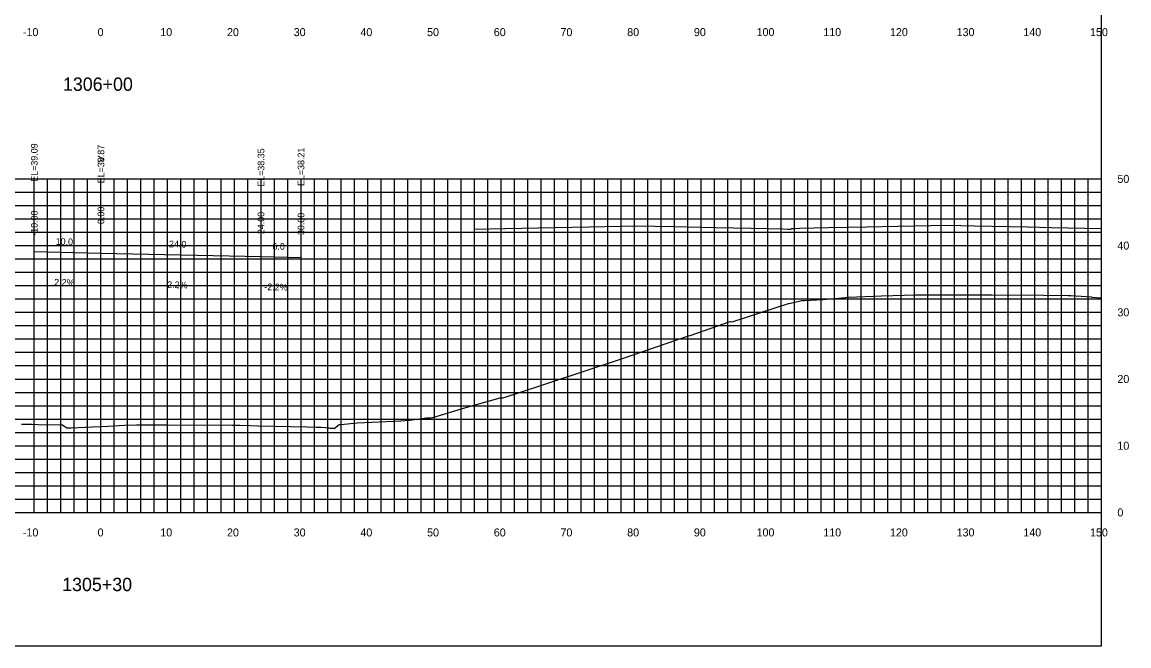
# Model space of a CAD drawing. Extents: x 1797714 to 1804825, y 249015 to 250269.
# Drawn here: x 1804292.3 to 1804458.3, y 249628.2 to 249721.7 of the extents above; entities that cross this region are included whole.
import ezdxf

# ---------------------------------------------------------------- set-up
doc = ezdxf.new("R2010")
doc.units = 0
for name, color, linetype in [('1', 7, 'Continuous'), ('10', 7, 'Continuous'), ('3', 7, 'Continuous'), ('31', 7, 'Continuous'), ('4', 7, 'Continuous'), ('60', 7, 'Continuous'), ('CL-CNST', 7, 'Continuous'), ('Level 62', 7, 'Continuous'), ('M-ROADS', 7, 'Continuous'), ('WEARING', 7, 'Continuous')]:
    doc.layers.add(name, color=color, linetype=linetype)

msp = doc.modelspace()

# ---------------------------------------------------------------- linework, layer by layer
for p, q in [((1804294.16, 249687.26), (1804294.16, 249689.26)), ((1804304.16, 249687.04), (1804304.16, 249689.04)), ((1804328.16, 249686.51), (1804328.16, 249688.51)), ((1804334.16, 249686.38), (1804334.16, 249688.38))]:
    msp.add_line(p, q)
msp.add_lwpolyline([(1804154.16, 249628.17), (1804454.16, 249628.17), (1804454.16, 249818.17), (1804154.16, 249818.17)], close=True)
at = {"layer": '60'}
for p, q in [((1804454.16, 249648.17), (1804454.16, 249698.17)), ((1804454.22, 249698.17), (1804454.16, 249698.17)), ((1804454.22, 249688.17), (1804454.16, 249688.17)), ((1804454.22, 249678.17), (1804454.16, 249678.17)), ((1804454.22, 249668.17), (1804454.16, 249668.17)), ((1804454.22, 249658.17), (1804454.16, 249658.17)), ((1804154.16, 249648.17), (1804454.16, 249648.17)), ((1804294.16, 249648.11), (1804294.16, 249648.17)), ((1804304.16, 249648.11), (1804304.16, 249648.17)), ((1804314.16, 249648.11), (1804314.16, 249648.17)), ((1804324.16, 249648.11), (1804324.16, 249648.17)), ((1804334.16, 249648.11), (1804334.16, 249648.17)), ((1804344.16, 249648.11), (1804344.16, 249648.17)), ((1804354.16, 249648.11), (1804354.16, 249648.17)), ((1804364.16, 249648.11), (1804364.16, 249648.17)), ((1804374.16, 249648.11), (1804374.16, 249648.17)), ((1804384.16, 249648.11), (1804384.16, 249648.17)), ((1804394.16, 249648.11), (1804394.16, 249648.17)), ((1804404.16, 249648.11), (1804404.16, 249648.17)), ((1804414.16, 249648.11), (1804414.16, 249648.17)), ((1804424.16, 249648.11), (1804424.16, 249648.17)), ((1804434.16, 249648.11), (1804434.16, 249648.17)), ((1804444.16, 249648.11), (1804444.16, 249648.17)), ((1804454.16, 249648.11), (1804454.16, 249648.17)), ((1804454.22, 249648.17), (1804454.16, 249648.17))]:
    msp.add_line(p, q, dxfattribs=at)
at = {"layer": 'CL-CNST'}
for points in [[(1804360.18, 249690.63), (1804364.73, 249690.73), (1804372.24, 249690.89), (1804377.4, 249691), (1804384.31, 249691.15), (1804390.08, 249691.02), (1804396.37, 249690.88), (1804401.64, 249690.77), (1804406.42, 249690.66), (1804407.1, 249690.64), (1804407.67, 249690.63)], [(1804294.16, 249687.26), (1804304.16, 249687.04), (1804328.16, 249686.51), (1804334.16, 249686.38)]]:
    msp.add_lwpolyline(points, dxfattribs=at)
at = {"layer": 'Level 62'}
for p, q in [((1804154.16, 249698.17), (1804454.16, 249698.17)), ((1804294.16, 249648.17), (1804294.16, 249698.17)), ((1804296.16, 249648.17), (1804296.16, 249698.17)), ((1804298.16, 249648.17), (1804298.16, 249698.17)), ((1804300.16, 249648.17), (1804300.16, 249698.17)), ((1804302.16, 249648.17), (1804302.16, 249698.17)), ((1804304.16, 249648.17), (1804304.16, 249698.17)), ((1804306.16, 249648.17), (1804306.16, 249698.17)), ((1804308.16, 249648.17), (1804308.16, 249698.17)), ((1804310.16, 249648.17), (1804310.16, 249698.17)), ((1804312.16, 249648.17), (1804312.16, 249698.17)), ((1804314.16, 249648.17), (1804314.16, 249698.17)), ((1804316.16, 249648.17), (1804316.16, 249698.17)), ((1804318.16, 249648.17), (1804318.16, 249698.17)), ((1804320.16, 249648.17), (1804320.16, 249698.17)), ((1804322.16, 249648.17), (1804322.16, 249698.17)), ((1804324.16, 249648.17), (1804324.16, 249698.17)), ((1804326.16, 249648.17), (1804326.16, 249698.17)), ((1804328.16, 249648.17), (1804328.16, 249698.17)), ((1804330.16, 249648.17), (1804330.16, 249698.17)), ((1804332.16, 249648.17), (1804332.16, 249698.17)), ((1804334.16, 249648.17), (1804334.16, 249698.17)), ((1804336.16, 249648.17), (1804336.16, 249698.17)), ((1804338.16, 249648.17), (1804338.16, 249698.17)), ((1804340.16, 249648.17), (1804340.16, 249698.17)), ((1804342.16, 249648.17), (1804342.16, 249698.17)), ((1804344.16, 249648.17), (1804344.16, 249698.17)), ((1804346.16, 249648.17), (1804346.16, 249698.17)), ((1804348.16, 249648.17), (1804348.16, 249698.17)), ((1804350.16, 249648.17), (1804350.16, 249698.17)), ((1804352.16, 249648.17), (1804352.16, 249698.17)), ((1804354.16, 249648.17), (1804354.16, 249698.17)), ((1804356.16, 249648.17), (1804356.16, 249698.17)), ((1804358.16, 249648.17), (1804358.16, 249698.17)), ((1804360.16, 249648.17), (1804360.16, 249698.17)), ((1804362.16, 249648.17), (1804362.16, 249698.17)), ((1804364.16, 249648.17), (1804364.16, 249698.17)), ((1804366.16, 249648.17), (1804366.16, 249698.17)), ((1804368.16, 249648.17), (1804368.16, 249698.17)), ((1804370.16, 249648.17), (1804370.16, 249698.17)), ((1804372.16, 249648.17), (1804372.16, 249698.17)), ((1804374.16, 249648.17), (1804374.16, 249698.17)), ((1804376.16, 249648.17), (1804376.16, 249698.17)), ((1804378.16, 249648.17), (1804378.16, 249698.17)), ((1804380.16, 249648.17), (1804380.16, 249698.17)), ((1804382.16, 249648.17), (1804382.16, 249698.17)), ((1804384.16, 249648.17), (1804384.16, 249698.17)), ((1804386.16, 249648.17), (1804386.16, 249698.17)), ((1804388.16, 249648.17), (1804388.16, 249698.17)), ((1804390.16, 249648.17), (1804390.16, 249698.17)), ((1804392.16, 249648.17), (1804392.16, 249698.17)), ((1804394.16, 249648.17), (1804394.16, 249698.17)), ((1804396.16, 249648.17), (1804396.16, 249698.17)), ((1804398.16, 249648.17), (1804398.16, 249698.17)), ((1804400.16, 249648.17), (1804400.16, 249698.17)), ((1804402.16, 249648.17), (1804402.16, 249698.17)), ((1804404.16, 249648.17), (1804404.16, 249698.17)), ((1804406.16, 249648.17), (1804406.16, 249698.17)), ((1804408.16, 249648.17), (1804408.16, 249698.17)), ((1804410.16, 249648.17), (1804410.16, 249698.17)), ((1804412.16, 249648.17), (1804412.16, 249698.17)), ((1804414.16, 249648.17), (1804414.16, 249698.17)), ((1804416.16, 249648.17), (1804416.16, 249698.17)), ((1804418.16, 249648.17), (1804418.16, 249698.17)), ((1804420.16, 249648.17), (1804420.16, 249698.17)), ((1804422.16, 249648.17), (1804422.16, 249698.17)), ((1804424.16, 249648.17), (1804424.16, 249698.17)), ((1804426.16, 249648.17), (1804426.16, 249698.17)), ((1804428.16, 249648.17), (1804428.16, 249698.17)), ((1804430.16, 249648.17), (1804430.16, 249698.17)), ((1804432.16, 249648.17), (1804432.16, 249698.17)), ((1804434.16, 249648.17), (1804434.16, 249698.17)), ((1804436.16, 249648.17), (1804436.16, 249698.17)), ((1804438.16, 249648.17), (1804438.16, 249698.17)), ((1804440.16, 249648.17), (1804440.16, 249698.17)), ((1804442.16, 249648.17), (1804442.16, 249698.17)), ((1804444.16, 249648.17), (1804444.16, 249698.17)), ((1804446.16, 249648.17), (1804446.16, 249698.17)), ((1804448.16, 249648.17), (1804448.16, 249698.17)), ((1804450.16, 249648.17), (1804450.16, 249698.17)), ((1804452.16, 249648.17), (1804452.16, 249698.17)), ((1804454.16, 249648.17), (1804454.16, 249698.17)), ((1804154.16, 249696.17), (1804454.16, 249696.17)), ((1804154.16, 249694.17), (1804454.16, 249694.17)), ((1804154.16, 249692.17), (1804454.16, 249692.17)), ((1804154.16, 249690.17), (1804454.16, 249690.17)), ((1804154.16, 249688.17), (1804454.16, 249688.17)), ((1804154.16, 249686.17), (1804454.16, 249686.17)), ((1804154.16, 249684.17), (1804454.16, 249684.17)), ((1804154.16, 249682.17), (1804454.16, 249682.17)), ((1804154.16, 249680.17), (1804454.16, 249680.17)), ((1804154.16, 249678.17), (1804454.16, 249678.17)), ((1804154.16, 249676.17), (1804454.16, 249676.17)), ((1804154.16, 249674.17), (1804454.16, 249674.17)), ((1804154.16, 249672.17), (1804454.16, 249672.17)), ((1804154.16, 249670.17), (1804454.16, 249670.17)), ((1804154.16, 249668.17), (1804454.16, 249668.17)), ((1804154.16, 249666.17), (1804454.16, 249666.17)), ((1804154.16, 249664.17), (1804454.16, 249664.17)), ((1804154.16, 249662.17), (1804454.16, 249662.17)), ((1804154.16, 249660.17), (1804454.16, 249660.17)), ((1804154.16, 249658.17), (1804454.16, 249658.17)), ((1804154.16, 249656.17), (1804454.16, 249656.17)), ((1804154.16, 249654.17), (1804454.16, 249654.17)), ((1804154.16, 249652.17), (1804454.16, 249652.17)), ((1804154.16, 249650.17), (1804454.16, 249650.17)), ((1804154.16, 249648.17), (1804454.16, 249648.17))]:
    msp.add_line(p, q, dxfattribs=at)
at = {"layer": 'M-ROADS'}
msp.add_lwpolyline([(1804292.26, 249661.4), (1804292.67, 249661.4), (1804293.75, 249661.38), (1804293.8, 249661.38), (1804294.77, 249661.34), (1804298.37, 249661.3), (1804298.61, 249661.13), (1804299.04, 249660.86), (1804299.43, 249660.85), (1804299.46, 249660.85), (1804299.49, 249660.85), (1804299.53, 249660.84), (1804299.57, 249660.84), (1804299.62, 249660.84), (1804299.67, 249660.83), (1804299.7, 249660.83), (1804302.89, 249660.99), (1804305.25, 249661.11), (1804307.72, 249661.25), (1804309.5, 249661.28), (1804309.99, 249661.29), (1804310.24, 249661.29), (1804310.28, 249661.29), (1804311.37, 249661.29), (1804312.73, 249661.31), (1804314.01, 249661.3), (1804323.82, 249661.24), (1804324.98, 249661.24), (1804326.56, 249661.2), (1804327.75, 249661.17), (1804335.01, 249660.99), (1804336.45, 249660.95), (1804337.1, 249660.93), (1804337.16, 249660.93), (1804337.81, 249660.88), (1804338.14, 249660.85), (1804338.34, 249660.84), (1804338.47, 249660.82), (1804338.56, 249660.82), (1804338.64, 249660.81), (1804338.69, 249660.81), (1804338.73, 249660.8), (1804338.74, 249660.8), (1804338.77, 249660.8), (1804338.8, 249660.8), (1804338.83, 249660.79), (1804338.85, 249660.79), (1804338.87, 249660.79), (1804338.89, 249660.79), (1804338.9, 249660.79), (1804338.92, 249660.79), (1804338.93, 249660.78), (1804338.94, 249660.78), (1804338.95, 249660.78), (1804338.96, 249660.78), (1804338.97, 249660.78), (1804339.11, 249660.76), (1804339.7, 249661.21), (1804339.73, 249661.23), (1804339.76, 249661.26), (1804339.87, 249661.35), (1804339.9, 249661.36), (1804340.11, 249661.36), (1804342.57, 249661.61), (1804349.1, 249661.88), (1804349.17, 249661.88), (1804350.34, 249662), (1804350.46, 249662.02), (1804352.99, 249662.36), (1804353.36, 249662.35), (1804353.53, 249662.37), (1804353.6, 249662.36), (1804353.91, 249662.42), (1804358.85, 249663.88), (1804364, 249665.34), (1804364.05, 249665.34), (1804364.49, 249665.33), (1804365.81, 249665.78), (1804365.87, 249665.78), (1804382.19, 249671.19), (1804392.25, 249674.66), (1804392.49, 249674.67), (1804398.49, 249676.77), (1804398.79, 249676.75), (1804407.24, 249679.47), (1804407.37, 249679.47), (1804409.25, 249679.95), (1804409.6, 249679.94), (1804412.38, 249680.07), (1804414.24, 249680.24), (1804416.25, 249680.43), (1804421.19, 249680.62), (1804426.31, 249680.81), (1804428.74, 249680.8), (1804431.99, 249680.79), (1804437.71, 249680.78), (1804445.46, 249680.73), (1804449.16, 249680.71), (1804449.59, 249680.68), (1804452.68, 249680.47), (1804452.74, 249680.46), (1804454.16, 249680.35)], dxfattribs=at)
at = {"layer": 'WEARING'}
msp.add_lwpolyline([(1804407.67, 249690.74), (1804408.24, 249690.75), (1804408.93, 249690.77), (1804413.24, 249690.86), (1804418.98, 249690.98), (1804423.65, 249691.08), (1804431.04, 249691.24), (1804435.15, 249691.14), (1804443.1, 249690.97), (1804446.65, 249690.89), (1804454.16, 249690.72)], dxfattribs=at)

# ---------------------------------------------------------------- texts
at = {"layer": '1'}
for s, p in [('1306+00', (1804298.46, 249711.37)), ('1305+30', (1804298.34, 249636.37))]:
    msp.add_text(s, height=2, dxfattribs=at).set_placement(p)
at = {"layer": '10'}
for s, p in [('-10', (1804292.46, 249719.57)), ('0', (1804303.66, 249719.57)), ('10', (1804313.06, 249719.57)), ('20', (1804323.06, 249719.57)), ('30', (1804333.06, 249719.57)), ('40', (1804343.06, 249719.57)), ('50', (1804353.06, 249719.57)), ('60', (1804363.06, 249719.57)), ('70', (1804373.06, 249719.57)), ('80', (1804383.06, 249719.57)), ('90', (1804393.06, 249719.57)), ('100', (1804402.46, 249719.57)), ('110', (1804412.46, 249719.57)), ('120', (1804422.46, 249719.57)), ('130', (1804432.46, 249719.57)), ('140', (1804442.46, 249719.57)), ('150', (1804452.46, 249719.57)), ('-10', (1804292.46, 249644.57)), ('0', (1804303.66, 249644.57)), ('10', (1804313.06, 249644.57)), ('20', (1804323.06, 249644.57)), ('30', (1804333.06, 249644.57)), ('40', (1804343.06, 249644.57)), ('50', (1804353.06, 249644.57)), ('60', (1804363.06, 249644.57)), ('70', (1804373.06, 249644.57)), ('80', (1804383.06, 249644.57)), ('90', (1804393.06, 249644.57)), ('100', (1804402.46, 249644.57)), ('110', (1804412.46, 249644.57)), ('120', (1804422.46, 249644.57)), ('130', (1804432.46, 249644.57)), ('140', (1804442.46, 249644.57)), ('150', (1804452.46, 249644.57))]:
    msp.add_text(s, height=1.2, dxfattribs=at).set_placement(p)
at = {"layer": '3'}
for s, p in [('EL=39.09', (1804294.66, 249697.73)), ('EL=38.87', (1804304.66, 249697.51)), ('EL=38.35', (1804328.66, 249696.98)), ('EL=38.21', (1804334.66, 249697.1)), ('0.00', (1804304.66, 249691.4)), ('-10.00', (1804294.66, 249689.64)), ('24.00', (1804328.66, 249689.88)), ('30.00', (1804334.66, 249689.75))]:
    msp.add_text(s, height=1, rotation=90, dxfattribs=at).set_placement(p)
at = {"layer": '31'}
for s, p in [('50', (1804456.56, 249697.57)), ('40', (1804456.56, 249687.57)), ('30', (1804456.56, 249677.57)), ('20', (1804456.56, 249667.57)), ('10', (1804456.56, 249657.57)), ('0', (1804456.56, 249647.57))]:
    msp.add_text(s, height=1.2, dxfattribs=at).set_placement(p)
at = {"layer": '4'}
for s, p in [('10.0', (1804297.36, 249688.29)), ('24.0', (1804314.36, 249687.92)), ('6.0', (1804329.86, 249687.57)), ('2.2%', (1804297.14, 249682.19)), ('-2.2%', (1804313.64, 249681.83)), ('-2.2%', (1804328.64, 249681.5))]:
    msp.add_text(s, height=1, rotation=358.7397, dxfattribs=at).set_placement(p)
at = {"layer": '60'}
msp.add_text('>', height=1.5, dxfattribs=at).set_placement((1804303.55, 249700.42))

doc.saveas('drawing.dxf')
